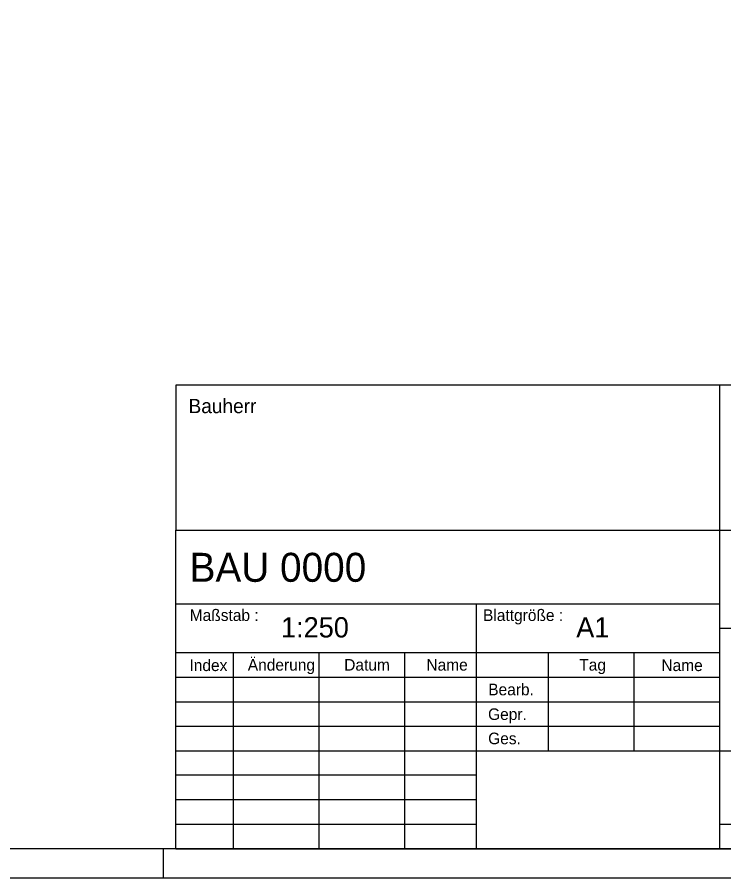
# Model space of a CAD drawing. Extents: x 0 to 210, y 0 to 148.
# Drawn here: x 157.69 to 188.16, y 0 to 37.12 of the extents above; entities that cross this region are included whole.
import ezdxf

# ---------------------------------------------------------------- set-up
doc = ezdxf.new("R2010")
doc.units = 0
doc.layers.add('90_Plankopf', color=7, linetype='Continuous')

msp = doc.modelspace()

# ---------------------------------------------------------------- linework, layer by layer
at = {"layer": '90_Plankopf'}
for p, q in [((209, 21.248), (164.53, 21.248)), ((164.53, 21.248), (164.53, 14.998)), ((188, 14.998), (188, 21.248)), ((164.53, 14.998), (209, 14.998)), ((164.53, 1.25), (164.53, 14.998)), ((164.53, 14.998), (209, 14.998)), ((188, 1.25), (188, 14.998)), ((164.53, 11.825), (188, 11.825)), ((177.501, 1.25), (177.501, 11.825)), ((188, 10.768), (209, 10.768)), ((164.53, 9.718), (188, 9.718)), ((167.001, 9.71), (167.001, 1.25)), ((170.707, 1.25), (170.707, 9.71)), ((174.412, 1.25), (174.412, 9.71)), ((180.589, 9.71), (180.589, 5.48)), ((184.294, 5.48), (184.294, 9.71)), ((164.53, 8.658), (188, 8.658)), ((164.53, 7.595), (188, 7.595)), ((164.53, 6.538), (188, 6.538)), ((164.53, 5.48), (188, 5.48)), ((164.53, 5.48), (188, 5.48)), ((177.501, 5.48), (188, 5.48)), ((188, 5.48), (209, 5.48)), ((177.501, 4.423), (164.53, 4.423)), ((177.501, 3.365), (164.53, 3.365)), ((164.53, 2.308), (177.501, 2.308)), ((188, 2.308), (209, 2.308)), ((164, 0), (164, 1.25)), ((209, 1.25), (164.53, 1.25)), ((164.53, 1.25), (177.501, 1.25)), ((167.45, 1.25), (209, 1.25)), ((167.45, 1.25), (209, 1.25))]:
    msp.add_line(p, q, dxfattribs=at)
for points in [[(0, 0), (210.25, 0), (210.25, 148.5), (0, 148.5)], [(6.25, 147.25), (209, 147.25), (209, 1.25), (6.25, 1.25)]]:
    msp.add_lwpolyline(points, close=True, dxfattribs=at)

# ---------------------------------------------------------------- texts
for s, height, p in [('Bauherr', 0.6159, (165.076, 20.044)), ('BAU 0000      ', 1.25, (165.123, 12.769)), ('Maßstab :', 0.5, (165.129, 11.079)), ('Blattgröße :', 0.49998, (177.779, 11.079)), ('1:250    ', 0.875, (169.065, 10.367)), ('A1       ', 0.875, (181.8, 10.367)), ('Index', 0.5, (165.117, 8.918)), ('Änderung', 0.5, (167.633, 8.937)), ('Datum', 0.5, (171.792, 8.937)), ('Name', 0.5, (175.337, 8.937)), ('Tag', 0.5, (181.931, 8.937)), ('Name', 0.5, (185.473, 8.918)), ('Bearb.', 0.5, (178.004, 7.873)), ('Gepr.', 0.5, (177.997, 6.808)), ('Ges.', 0.5, (178.001, 5.762))]:
    msp.add_text(s, height=height, dxfattribs=at).set_placement(p)

doc.saveas('drawing.dxf')
